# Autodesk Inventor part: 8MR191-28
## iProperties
Created: 2008-09
Part Number: 8MR191-28
Document SubType Name: Modeling
Designer: Darius
Author: Darius
Translation Standard: STEP AP203
File Name: 8MR191-28.STEP
Preprocessor: SolidWorks 2003240
Postprocessor: Build: 272, Release: 10 SP3a - Date: Thu 12/15/2005
Sent Units: MILLIMETERS
Uncertainty: 1e-05
